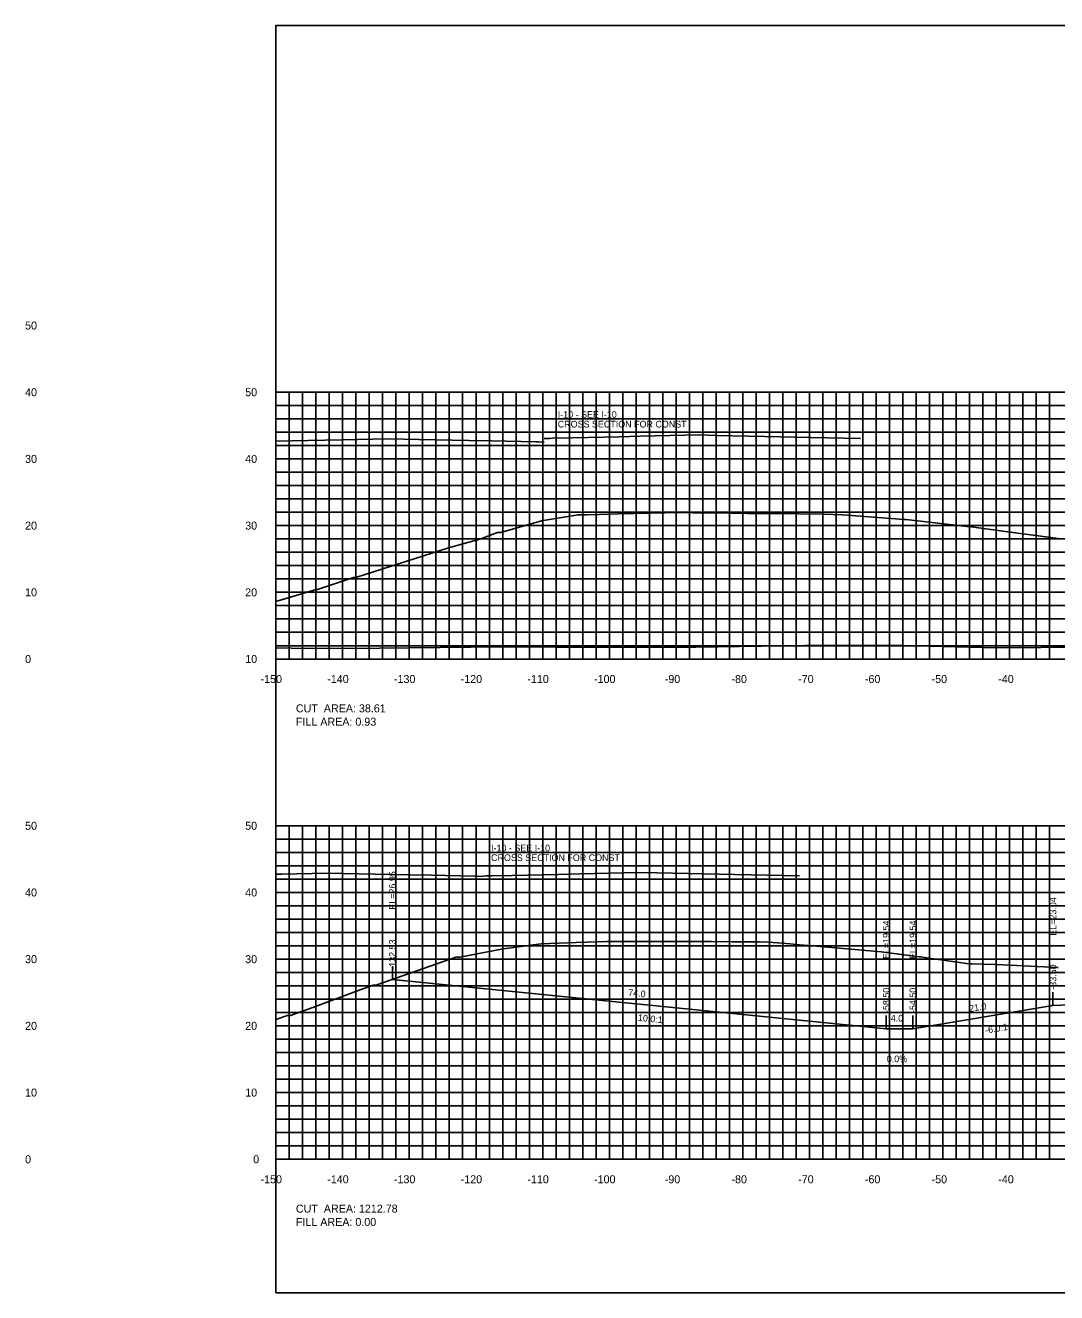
# Model space of a CAD drawing. Extents: x 1797305 to 1804485, y 245831 to 250849.
# Drawn here: x 1802783.4 to 1802938.1, y 250079.4 to 250269.4 of the extents above; entities that cross this region are included whole.
import ezdxf

# ---------------------------------------------------------------- set-up
doc = ezdxf.new("R2010")
doc.units = 0
for name, color, linetype in [('10', 7, 'Continuous'), ('29', 7, 'Continuous'), ('60', 7, 'Continuous'), ('BASE', 7, 'Continuous'), ('CL-CNST', 7, 'Continuous'), ('EDPV-LINE', 7, 'Continuous'), ('Level 31', 7, 'Continuous'), ('LIMT-CSLINE', 7, 'Continuous'), ('M-ROADS', 7, 'Continuous')]:
    doc.layers.add(name, color=color, linetype=linetype)

msp = doc.modelspace()

# ---------------------------------------------------------------- linework, layer by layer
for p, q in [((1802838.47, 250126.38), (1802838.47, 250128.38)), ((1802937.5, 250122.48), (1802937.5, 250124.48)), ((1802912.5, 250118.98), (1802912.5, 250120.98)), ((1802916.5, 250118.98), (1802916.5, 250120.98))]:
    msp.add_line(p, q)
msp.add_lwpolyline([(1802821, 250079.43), (1803121, 250079.43), (1803121, 250269.43), (1802821, 250269.43)], close=True)
at = {"layer": '29'}
for p, q in [((1802821, 250214.43), (1803121, 250214.43)), ((1802821, 250174.43), (1802821, 250214.43)), ((1802823, 250174.43), (1802823, 250214.43)), ((1802825, 250174.43), (1802825, 250214.43)), ((1802827, 250174.43), (1802827, 250214.43)), ((1802829, 250174.43), (1802829, 250214.43)), ((1802831, 250174.43), (1802831, 250214.43)), ((1802833, 250174.43), (1802833, 250214.43)), ((1802835, 250174.43), (1802835, 250214.43)), ((1802837, 250174.43), (1802837, 250214.43)), ((1802839, 250174.43), (1802839, 250214.43)), ((1802841, 250174.43), (1802841, 250214.43)), ((1802843, 250174.43), (1802843, 250214.43)), ((1802845, 250174.43), (1802845, 250214.43)), ((1802847, 250174.43), (1802847, 250214.43)), ((1802849, 250174.43), (1802849, 250214.43)), ((1802851, 250174.43), (1802851, 250214.43)), ((1802853, 250174.43), (1802853, 250214.43)), ((1802855, 250174.43), (1802855, 250214.43)), ((1802857, 250174.43), (1802857, 250214.43)), ((1802859, 250174.43), (1802859, 250214.43)), ((1802861, 250174.43), (1802861, 250214.43)), ((1802863, 250174.43), (1802863, 250214.43)), ((1802865, 250174.43), (1802865, 250214.43)), ((1802867, 250174.43), (1802867, 250214.43)), ((1802869, 250174.43), (1802869, 250214.43)), ((1802871, 250174.43), (1802871, 250214.43)), ((1802873, 250174.43), (1802873, 250214.43)), ((1802875, 250174.43), (1802875, 250214.43)), ((1802877, 250174.43), (1802877, 250214.43)), ((1802879, 250174.43), (1802879, 250214.43)), ((1802881, 250174.43), (1802881, 250214.43)), ((1802883, 250174.43), (1802883, 250214.43)), ((1802885, 250174.43), (1802885, 250214.43)), ((1802887, 250174.43), (1802887, 250214.43)), ((1802889, 250174.43), (1802889, 250214.43)), ((1802891, 250174.43), (1802891, 250214.43)), ((1802893, 250174.43), (1802893, 250214.43)), ((1802895, 250174.43), (1802895, 250214.43)), ((1802897, 250174.43), (1802897, 250214.43)), ((1802899, 250174.43), (1802899, 250214.43)), ((1802901, 250174.43), (1802901, 250214.43)), ((1802903, 250174.43), (1802903, 250214.43)), ((1802905, 250174.43), (1802905, 250214.43)), ((1802907, 250174.43), (1802907, 250214.43)), ((1802909, 250174.43), (1802909, 250214.43)), ((1802911, 250174.43), (1802911, 250214.43)), ((1802913, 250174.43), (1802913, 250214.43)), ((1802915, 250174.43), (1802915, 250214.43)), ((1802917, 250174.43), (1802917, 250214.43)), ((1802919, 250174.43), (1802919, 250214.43)), ((1802921, 250174.43), (1802921, 250214.43)), ((1802923, 250174.43), (1802923, 250214.43)), ((1802925, 250174.43), (1802925, 250214.43)), ((1802927, 250174.43), (1802927, 250214.43)), ((1802929, 250174.43), (1802929, 250214.43)), ((1802931, 250174.43), (1802931, 250214.43)), ((1802933, 250174.43), (1802933, 250214.43)), ((1802935, 250174.43), (1802935, 250214.43)), ((1802937, 250174.43), (1802937, 250214.43)), ((1802821, 250212.43), (1803121, 250212.43)), ((1802821, 250210.43), (1803121, 250210.43)), ((1802821, 250208.43), (1803121, 250208.43)), ((1802821, 250206.43), (1803121, 250206.43)), ((1802821, 250204.43), (1803121, 250204.43)), ((1802821, 250202.43), (1803121, 250202.43)), ((1802821, 250200.43), (1803121, 250200.43)), ((1802821, 250198.43), (1803121, 250198.43)), ((1802821, 250196.43), (1803121, 250196.43)), ((1802821, 250194.43), (1803121, 250194.43)), ((1802821, 250192.43), (1803121, 250192.43)), ((1802821, 250190.43), (1803121, 250190.43)), ((1802821, 250188.43), (1803121, 250188.43)), ((1802821, 250186.43), (1803121, 250186.43)), ((1802821, 250184.43), (1803121, 250184.43)), ((1802821, 250182.43), (1803121, 250182.43)), ((1802821, 250180.43), (1803121, 250180.43)), ((1802821, 250178.43), (1803121, 250178.43)), ((1802821, 250176.43), (1803121, 250176.43)), ((1802821, 250174.43), (1803121, 250174.43)), ((1802821, 250149.43), (1803121, 250149.43)), ((1802821, 250099.43), (1802821, 250149.43)), ((1802823, 250099.43), (1802823, 250149.43)), ((1802825, 250099.43), (1802825, 250149.43)), ((1802827, 250099.43), (1802827, 250149.43)), ((1802829, 250099.43), (1802829, 250149.43)), ((1802831, 250099.43), (1802831, 250149.43)), ((1802833, 250099.43), (1802833, 250149.43)), ((1802835, 250099.43), (1802835, 250149.43)), ((1802837, 250099.43), (1802837, 250149.43)), ((1802839, 250099.43), (1802839, 250149.43)), ((1802841, 250099.43), (1802841, 250149.43)), ((1802843, 250099.43), (1802843, 250149.43)), ((1802845, 250099.43), (1802845, 250149.43)), ((1802847, 250099.43), (1802847, 250149.43)), ((1802849, 250099.43), (1802849, 250149.43)), ((1802851, 250099.43), (1802851, 250149.43)), ((1802853, 250099.43), (1802853, 250149.43)), ((1802855, 250099.43), (1802855, 250149.43)), ((1802857, 250099.43), (1802857, 250149.43)), ((1802859, 250099.43), (1802859, 250149.43)), ((1802861, 250099.43), (1802861, 250149.43)), ((1802863, 250099.43), (1802863, 250149.43)), ((1802865, 250099.43), (1802865, 250149.43)), ((1802867, 250099.43), (1802867, 250149.43)), ((1802869, 250099.43), (1802869, 250149.43)), ((1802871, 250099.43), (1802871, 250149.43)), ((1802873, 250099.43), (1802873, 250149.43)), ((1802875, 250099.43), (1802875, 250149.43)), ((1802877, 250099.43), (1802877, 250149.43)), ((1802879, 250099.43), (1802879, 250149.43)), ((1802881, 250099.43), (1802881, 250149.43)), ((1802883, 250099.43), (1802883, 250149.43)), ((1802885, 250099.43), (1802885, 250149.43)), ((1802887, 250099.43), (1802887, 250149.43)), ((1802889, 250099.43), (1802889, 250149.43)), ((1802891, 250099.43), (1802891, 250149.43)), ((1802893, 250099.43), (1802893, 250149.43)), ((1802895, 250099.43), (1802895, 250149.43)), ((1802897, 250099.43), (1802897, 250149.43)), ((1802899, 250099.43), (1802899, 250149.43)), ((1802901, 250099.43), (1802901, 250149.43)), ((1802903, 250099.43), (1802903, 250149.43)), ((1802905, 250099.43), (1802905, 250149.43)), ((1802907, 250099.43), (1802907, 250149.43)), ((1802909, 250099.43), (1802909, 250149.43)), ((1802911, 250099.43), (1802911, 250149.43)), ((1802913, 250099.43), (1802913, 250149.43)), ((1802915, 250099.43), (1802915, 250149.43)), ((1802917, 250099.43), (1802917, 250149.43)), ((1802919, 250099.43), (1802919, 250149.43)), ((1802921, 250099.43), (1802921, 250149.43)), ((1802923, 250099.43), (1802923, 250149.43)), ((1802925, 250099.43), (1802925, 250149.43)), ((1802927, 250099.43), (1802927, 250149.43)), ((1802929, 250099.43), (1802929, 250149.43)), ((1802931, 250099.43), (1802931, 250149.43)), ((1802933, 250099.43), (1802933, 250149.43)), ((1802935, 250099.43), (1802935, 250149.43)), ((1802937, 250099.43), (1802937, 250149.43)), ((1802821, 250147.43), (1803121, 250147.43)), ((1802821, 250145.43), (1803121, 250145.43)), ((1802821, 250143.43), (1803121, 250143.43)), ((1802821, 250141.43), (1803121, 250141.43)), ((1802821, 250139.43), (1803121, 250139.43)), ((1802821, 250137.43), (1803121, 250137.43)), ((1802821, 250135.43), (1803121, 250135.43)), ((1802821, 250133.43), (1803121, 250133.43)), ((1802821, 250131.43), (1803121, 250131.43)), ((1802821, 250129.43), (1803121, 250129.43)), ((1802821, 250127.43), (1803121, 250127.43)), ((1802821, 250125.43), (1803121, 250125.43)), ((1802821, 250123.43), (1803121, 250123.43)), ((1802821, 250121.43), (1803121, 250121.43)), ((1802821, 250119.43), (1803121, 250119.43)), ((1802821, 250117.43), (1803121, 250117.43)), ((1802821, 250115.43), (1803121, 250115.43)), ((1802821, 250113.43), (1803121, 250113.43)), ((1802821, 250111.43), (1803121, 250111.43)), ((1802821, 250109.43), (1803121, 250109.43)), ((1802821, 250107.43), (1803121, 250107.43)), ((1802821, 250105.43), (1803121, 250105.43)), ((1802821, 250103.43), (1803121, 250103.43)), ((1802821, 250101.43), (1803121, 250101.43)), ((1802821, 250099.43), (1803121, 250099.43))]:
    msp.add_line(p, q, dxfattribs=at)
at = {"layer": 'CL-CNST'}
for points in [[(1802821, 250207.1), (1802825.81, 250207.2), (1802830.87, 250207.31), (1802837.86, 250207.46), (1802842.42, 250207.36), (1802849.91, 250207.2), (1802853.31, 250207.12), (1802859.95, 250206.98), (1802860.34, 250206.97), (1802861.21, 250206.95)], [(1802861.21, 250207.49), (1802862.08, 250207.51), (1802862.46, 250207.52), (1802865.42, 250207.59), (1802872.51, 250207.75), (1802875.6, 250207.82), (1802884.56, 250208.02), (1802887.14, 250207.96), (1802896.61, 250207.76), (1802898.69, 250207.71), (1802908.66, 250207.5)], [(1802821, 250176.09), (1802825.63, 250176.01), (1802836.51, 250176.07), (1802854.79, 250176.25), (1802871.5, 250176.14), (1802883.94, 250176.21), (1802900.36, 250176.47), (1802913.1, 250176.53), (1802929.15, 250176.11), (1802942.26, 250176.19), (1802965.49, 250175.42), (1802971.42, 250175.46), (1802994.91, 250175.46), (1803000.58, 250175.49), (1803023.88, 250175.49), (1803029.74, 250175.52), (1803052.2, 250175.53), (1803058.9, 250175.54), (1803066.05, 250175.54), (1803088.05, 250175.56), (1803096.69, 250175.54), (1803117.21, 250175.56), (1803121, 250175.54)], [(1802821, 250142.17), (1802821.91, 250142.19), (1802828.71, 250142.34), (1802833.45, 250142.23), (1802840.76, 250142.08), (1802844.32, 250142), (1802850.8, 250141.86), (1802851.21, 250141.85), (1802852.05, 250141.83)], [(1802852.06, 250141.89), (1802852.46, 250141.9), (1802853.31, 250141.92), (1802856.43, 250141.99), (1802863.35, 250142.14), (1802866.64, 250142.22), (1802875.4, 250142.41), (1802878.18, 250142.35), (1802887.45, 250142.15), (1802889.73, 250142.11), (1802899.5, 250141.9)], [(1802838.47, 250126.38), (1802912.5, 250118.98), (1802916.5, 250118.98), (1802937.5, 250122.48), (1802943, 250122.7), (1802947, 250122.63), (1802971, 250122.1), (1802979, 250121.88), (1802984.5, 250121.66), (1803005.5, 250118.16), (1803009.5, 250118.16), (1803018.77, 250120.48)]]:
    msp.add_lwpolyline(points, dxfattribs=at)
at = {"layer": 'Level 31'}
for p, q in [((1802820.94, 250214.43), (1802821, 250214.43)), ((1802821, 250174.43), (1802821, 250214.43)), ((1802820.94, 250204.43), (1802821, 250204.43)), ((1802820.94, 250194.43), (1802821, 250194.43)), ((1802820.94, 250184.43), (1802821, 250184.43)), ((1802820.94, 250174.43), (1802821, 250174.43)), ((1802821, 250174.43), (1803121, 250174.43)), ((1802821, 250174.37), (1802821, 250174.43)), ((1802831, 250174.37), (1802831, 250174.43)), ((1802841, 250174.37), (1802841, 250174.43)), ((1802851, 250174.37), (1802851, 250174.43)), ((1802861, 250174.37), (1802861, 250174.43)), ((1802871, 250174.37), (1802871, 250174.43)), ((1802881, 250174.37), (1802881, 250174.43)), ((1802891, 250174.37), (1802891, 250174.43)), ((1802901, 250174.37), (1802901, 250174.43)), ((1802911, 250174.37), (1802911, 250174.43)), ((1802921, 250174.37), (1802921, 250174.43)), ((1802931, 250174.37), (1802931, 250174.43)), ((1802820.94, 250149.43), (1802821, 250149.43)), ((1802821, 250099.43), (1802821, 250149.43)), ((1802820.94, 250139.43), (1802821, 250139.43)), ((1802820.94, 250129.43), (1802821, 250129.43)), ((1802820.94, 250119.43), (1802821, 250119.43)), ((1802820.94, 250109.43), (1802821, 250109.43)), ((1802820.94, 250099.43), (1802821, 250099.43)), ((1802821, 250099.43), (1803121, 250099.43)), ((1802821, 250099.37), (1802821, 250099.43)), ((1802831, 250099.37), (1802831, 250099.43)), ((1802841, 250099.37), (1802841, 250099.43)), ((1802851, 250099.37), (1802851, 250099.43)), ((1802861, 250099.37), (1802861, 250099.43)), ((1802871, 250099.37), (1802871, 250099.43)), ((1802881, 250099.37), (1802881, 250099.43)), ((1802891, 250099.37), (1802891, 250099.43)), ((1802901, 250099.37), (1802901, 250099.43)), ((1802911, 250099.37), (1802911, 250099.43)), ((1802921, 250099.37), (1802921, 250099.43)), ((1802931, 250099.37), (1802931, 250099.43))]:
    msp.add_line(p, q, dxfattribs=at)
at = {"layer": 'M-ROADS'}
for points in [[(1802821, 250183.03), (1802827.02, 250184.86), (1802827.22, 250184.85), (1802832.64, 250186.67), (1802832.93, 250186.67), (1802833.15, 250186.68), (1802846.9, 250191.08), (1802851.56, 250192.38), (1802854.21, 250193.42), (1802854.43, 250193.42), (1802854.72, 250193.42), (1802860.83, 250195.13), (1802861.1, 250195.19), (1802866.3, 250196.05), (1802867.39, 250196.07), (1802867.59, 250196.07), (1802869.45, 250196.12), (1802872.36, 250196.2), (1802879.23, 250196.37), (1802879.34, 250196.37), (1802880.52, 250196.42), (1802883.52, 250196.37), (1802889.25, 250196.29), (1802890.1, 250196.28), (1802891.7, 250196.26), (1802893.7, 250196.25), (1802894.35, 250196.25), (1802899.39, 250196.21), (1802903.23, 250196.17), (1802905.92, 250196.03), (1802906.74, 250195.99), (1802907.29, 250195.94), (1802915.19, 250195.34), (1802915.45, 250195.34), (1802924.64, 250194.28), (1802924.87, 250194.28), (1802930.75, 250193.52), (1802937.93, 250192.53), (1802938.27, 250192.48)], [(1802821, 250120.39), (1802822.72, 250120.99), (1802823.22, 250120.99), (1802823.22, 250120.99), (1802823.47, 250121.08), (1802823.57, 250121.12), (1802826.54, 250122.2), (1802833.1, 250124.64), (1802835.59, 250125.52), (1802836.05, 250125.53), (1802836.12, 250125.56), (1802848.11, 250129.76), (1802848.29, 250129.75), (1802848.59, 250129.75), (1802855.08, 250130.99), (1802856.32, 250131.15), (1802858.48, 250131.44), (1802860.75, 250131.74), (1802866.04, 250131.92), (1802870.62, 250132.07), (1802875.47, 250132.07), (1802882.02, 250132.07), (1802882.93, 250132.07), (1802884.7, 250132.06), (1802886.25, 250132.06), (1802889.39, 250132.05), (1802893.51, 250132.04), (1802894.76, 250131.96), (1802897.02, 250131.81), (1802898.57, 250131.68), (1802899.5, 250131.6), (1802902.07, 250131.37), (1802911.76, 250130.55), (1802917.43, 250129.76), (1802917.66, 250129.76), (1802918.95, 250129.58), (1802924.89, 250128.72), (1802925.2, 250128.72), (1802925.38, 250128.72), (1802929.02, 250128.61), (1802937.2, 250128.23), (1802938.02, 250128.19), (1802938.29, 250128.19)]]:
    msp.add_lwpolyline(points, dxfattribs=at)

# ---------------------------------------------------------------- texts
for s, rotation, p in [('10.0:1', 354.2894, (1802875.24, 250120.19)), ('-6.0:1', 9.4623, (1802927.41, 250118.26))]:
    msp.add_text(s, height=1, rotation=rotation).set_placement(p)
at = {"layer": '10'}
for s, p in [('-150', (1802818.7, 250170.83)), ('-140', (1802828.7, 250170.83)), ('-130', (1802838.7, 250170.83)), ('-120', (1802848.7, 250170.83)), ('-110', (1802858.7, 250170.83)), ('-100', (1802868.7, 250170.83)), ('-90', (1802879.3, 250170.83)), ('-80', (1802889.3, 250170.83)), ('-70', (1802899.3, 250170.83)), ('-60', (1802909.3, 250170.83)), ('-50', (1802919.3, 250170.83)), ('-40', (1802929.3, 250170.83)), ('-150', (1802818.7, 250095.83)), ('-140', (1802828.7, 250095.83)), ('-130', (1802838.7, 250095.83)), ('-120', (1802848.7, 250095.83)), ('-110', (1802858.7, 250095.83)), ('-100', (1802868.7, 250095.83)), ('-90', (1802879.3, 250095.83)), ('-80', (1802889.3, 250095.83)), ('-70', (1802899.3, 250095.83)), ('-60', (1802909.3, 250095.83)), ('-50', (1802919.3, 250095.83)), ('-40', (1802929.3, 250095.83))]:
    msp.add_text(s, height=1.2, dxfattribs=at).set_placement(p)
at = {"layer": '60'}
for s, p in [('50', (1802783.4, 250223.83)), ('40', (1802783.4, 250213.83)), ('50', (1802816.4, 250213.83)), ('30', (1802783.4, 250203.83)), ('40', (1802816.4, 250203.83)), ('20', (1802783.4, 250193.83)), ('30', (1802816.4, 250193.83)), ('10', (1802783.4, 250183.83)), ('20', (1802816.4, 250183.83)), ('0', (1802783.4, 250173.83)), ('10', (1802816.4, 250173.83)), ('50', (1802783.4, 250148.83)), ('50', (1802816.4, 250148.83)), ('40', (1802783.4, 250138.83)), ('40', (1802816.4, 250138.83)), ('30', (1802783.4, 250128.83)), ('30', (1802816.4, 250128.83)), ('20', (1802783.4, 250118.83)), ('20', (1802816.4, 250118.83)), ('10', (1802783.4, 250108.83)), ('10', (1802816.4, 250108.83)), ('0', (1802783.4, 250098.83)), ('0', (1802817.6, 250098.83))]:
    msp.add_text(s, height=1.2, dxfattribs=at).set_placement(p)
at = {"layer": 'BASE'}
for s, rotation, p in [('74.0', 354.2894, (1802873.78, 250123.95)), ('21.0', 9.4623, (1802925.03, 250121.51))]:
    msp.add_text(s, height=1, rotation=rotation, dxfattribs=at).set_placement(p)
for s, p in [('4.0', (1802913.18, 250120.08)), ('0.0%', (1802912.59, 250113.98))]:
    msp.add_text(s, height=1, dxfattribs=at).set_placement(p)
at = {"layer": 'EDPV-LINE'}
for s, p in [('CUT  AREA: 38.61', (1802824, 250166.43)), ('FILL AREA: 0.93', (1802824, 250164.43)), ('CUT  AREA: 1212.78', (1802824, 250091.43)), ('FILL AREA: 0.00', (1802824, 250089.43))]:
    msp.add_text(s, height=1.2, dxfattribs=at).set_placement(p)
at = {"layer": 'Level 31'}
for p in [(1802821, 250174.43), (1802821, 250099.43)]:
    msp.add_text('-', height=0.0001, dxfattribs=at).set_placement(p)
at = {"layer": 'LIMT-CSLINE'}
for s, p in [('I-10 - SEE I-10', (1802863.26, 250210.59)), ('CROSS SECTION FOR CONST ', (1802863.26, 250209.14)), ('I-10 - SEE I-10', (1802853.26, 250145.59)), ('CROSS SECTION FOR CONST ', (1802853.26, 250144.14))]:
    msp.add_text(s, height=1, dxfattribs=at).set_placement(p)
for s, p in [('EL=26.95', (1802838.97, 250136.85)), ('EL=23.04', (1802938, 250132.95)), ('EL=19.54', (1802913, 250129.45)), ('EL=19.54', (1802917, 250129.45)), ('-132.53', (1802838.97, 250127.84)), ('-33.50', (1802938, 250124.85)), ('-58.50', (1802913, 250121.35)), ('-54.50', (1802917, 250121.35))]:
    msp.add_text(s, height=1, rotation=90, dxfattribs=at).set_placement(p)

doc.saveas('drawing.dxf')
